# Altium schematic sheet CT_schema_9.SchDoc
size 147 x 119 mm
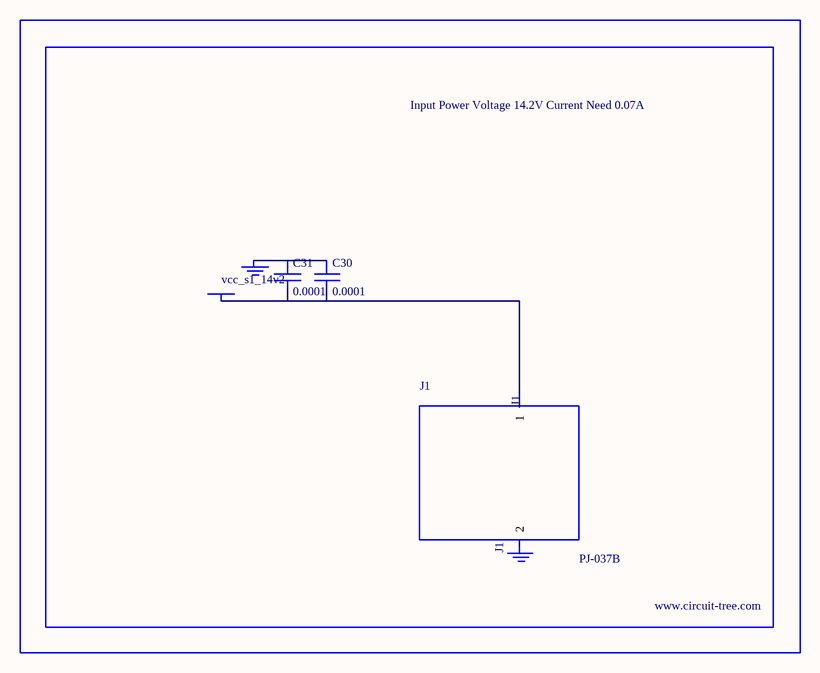
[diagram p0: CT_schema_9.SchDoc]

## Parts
BORDER8  (no value)
C30  0.0001  [EXV-9H]
C31  0.0001  [EXV-9H]
GND_INSTANCE_8_0  (no value)
GND_INSTANCE_8_1  (no value)
J1  PJ-037B  [PJ-037B_PACKAGE]
POWER_INSTANCE_8_0  vcc_s1_14v2

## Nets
NetC30_1: C30.1 C31.1 GND_INSTANCE_8_0.0(GND)
NetC30_2: C30.2 C31.2 J1.1 POWER_INSTANCE_8_0.0(PWR)

Not connected (* = marked no-connect by the designer): GND_INSTANCE_8_1 0(GND); J1 2

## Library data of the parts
BORDER8 = BORDER_PAGE8
C30 C31 = EDK107M035A9HAA
GND_INSTANCE_8_0 GND_INSTANCE_8_1 = GND
POWER_INSTANCE_8_0 = PWR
